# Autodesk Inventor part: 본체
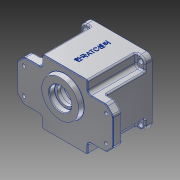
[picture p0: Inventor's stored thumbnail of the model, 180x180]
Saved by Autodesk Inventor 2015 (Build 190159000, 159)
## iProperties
Created: 2016-02
Part Number: 본체
Material: 알루미늄 6061
Document SubType Name: Modeling
Designer: Administrator
Density: 2.7 g/cm^3
Appearance: 알루미늄 - 평지
Mass: 873.852 g
Surface Area: 761.587 cm^2
Volume: 323.649 cm^3
Author: Administrator
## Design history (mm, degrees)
sketch "스케치1"
  geometry: L1 (47, -47)-(-47, -47); L2 (-47, -47)-(-47, 47); L3 (-47, 47)-(47, 47); L4 (47, 47)-(47, -47); L5 (47, -47)-(-47, 47); L6 (-47, -47)-(47, 47); 1 further point
  constraints: 12 end point, 2 midpoint, 2 parallel, 1 horizontal, 1 perpendicular
  dimensions: "d0" = 94 distance of L2.end L3.end; "d1" = 94 distance of L1.end L2.end
extrude "돌출1" new body sketch "스케치1" distance "d2" = 80; taper "d3" = 0 deg
sketch "스케치2"
  geometry: L1 (47, 47)-(-47, 47) reference; L2 (-47, 47)-(-47, -47) reference; L3 (-47, -47)-(47, -47) reference; L4 (47, -47)-(47, 47) reference; L5 (-47, 47)-(-33, 47); L6 (-33, 47)-(-33, 30); L7 (-33, 30)-(-47, 30); L8 (-47, 30)-(-47, 47); L9 (47, 47)-(33, 47); L10 (33, 47)-(33, 30); L11 (33, 30)-(47, 30); L12 (47, 30)-(47, 47); L13 (47, -47)-(33, -47); L14 (33, -47)-(33, -30); L15 (33, -30)-(47, -30); L16 (47, -30)-(47, -47); L17 (-47, -47)-(-33, -47); L18 (-33, -47)-(-33, -30); L19 (-33, -30)-(-47, -30); L20 (-47, -30)-(-47, -47); 1 further point
  constraints: 32 end point, 8 parallel, 4 horizontal, 4 perpendicular, 4 point on line
  dimensions: "d4" = 60 distance between parallel lines of L19 L7; "d5" = 30 distance from line of L7 point (0, 0) (= 0.5 x d4); "d6" = 66 distance between parallel lines of L10 L6; "d7" = 33 distance from line of point (0, 0) L10 (= 0.5 x d6)
extrude "돌출2" cut sketch "스케치2" distance "d8" = 70; taper "d9" = 0 deg
fillet "모깎기1" dims "d10" = 8
sketch "스케치3"
  geometry: C1 r 3.5 at (-40, 40); C2 r 3.5 at (40, 40); C3 r 3.5 at (40, -40); C4 r 3.5 at (-40, -40); A1 r 8 centre (-39, 39) between (-39, 47) and (-47, 39) reference; A2 r 8 centre (39, 39) between (47, 39) and (39, 47) reference; A3 r 8 centre (39, -39) between (39, -47) and (47, -39) reference; A4 r 8 centre (-39, -39) between (-47, -39) and (-39, -47) reference; 1 further point
  constraints: 4 centre point
  dimensions: "d11" = 78 distance of A2.centre A1.centre (derived); "d12" = 78 distance of A3.centre A2.centre (derived); "d13" = 7 diameter of C1; "d14" = 7 diameter of C2; "d15" = 7 diameter of C3; "d16" = 7 diameter of C4; "d17" = 80 distance of C2.centre C1.centre; "d18" = 80 distance of C3.centre C2.centre; "d19" = 40 horizontal distance of point (0, 0) C2.centre (= 0.5 x d17); "d20" = 40 horizontal distance of C2.centre point (0, 0) (= 0.5 x d18); "d21" = 40 horizontal distance of C3.centre point (0, 0) (= d19); "d22" = 40 horizontal distance of point (0, 0) C1.centre; "d23" = 40 horizontal distance of C4.centre point (0, 0) (= d22); "d24" = 40 horizontal distance of point (0, 0) C4.centre (= d21)
extrude "돌출3" cut sketch "스케치3" stored distance "d25" = 67; taper "d26" = 0 deg
sketch "스케치4"
  geometry: L1 (33, -47)-(33, -30) reference; L2 (33, -30)-(47, -30) reference; L3 (47, -30)-(47, 30) reference; L4 (47, 30)-(33, 30) reference; L5 (33, 30)-(33, 47) reference; L6 (33, 47)-(-33, 47) reference; L7 (-33, 47)-(-33, 30) reference; L8 (-33, 30)-(-47, 30) reference; L9 (-47, 30)-(-47, -30) reference; L10 (-47, -30)-(-33, -30) reference; L11 (-33, -30)-(-33, -47) reference; L12 (-33, -47)-(33, -47) reference; L13 (-47, 30)-(-70, 30); L14 (-70, 30)-(-70, -30); L15 (-70, -30)-(-47, -30); L16 (-47, -30)-(-47, 30); L17 (47, 30)-(70, 30); L18 (70, 30)-(70, -30); L19 (70, -30)-(47, -30); L20 (47, -30)-(47, 30); 1 further point
  constraints: 16 end point, 4 parallel, 2 horizontal, 2 perpendicular
  dimensions: "d27" = 140 distance between parallel lines of L18 L14; "d28" = 94 distance between parallel lines of L3 L9 (derived); "d29" = 23 distance between parallel lines of L9 L14 (= -0.5 x d28 + 0.5 x d27)
extrude "돌출4" join sketch "스케치4" distance "d30" = 13; taper "d31" = 0 deg
sketch "스케치6"
  geometry: L1 (60, -19)-(-60, -19); L2 (-60, -19)-(-60, 19); L3 (-60, 19)-(60, 19); L4 (60, 19)-(60, -19); L5 (60, -19)-(-60, 19); L6 (-60, -19)-(60, 19); 5 further points
  constraints: 12 end point, 4 coincident, 2 midpoint, 2 parallel, 1 horizontal, 1 perpendicular
  dimensions: "d34" = 38 distance between parallel lines of L3 L1; "d35" = 120 distance between parallel lines of L4 L2
hole "구멍1" sketch "스케치6" at (-60, -19), (-60, 19), (60, 19), (60, -19) diameter "d36" = 5; stored, may be unused: countersink angle "d40" = 90 deg, drill point angle "d42" = 0 deg; dims "d37" = 6, "d38" = 9, "d39" = 4, "d41" = 13
chamfer "모따기1" distance "d43" = 10; stored, may be unused: second distance "d44" = 2, angle "d45" = 45 deg
sketch "스케치7"
  geometry: C1 r 28 at (0, 11); 1 further point
  constraints: 1 centre point, 1 vertical alignment
  dimensions: "d46" = 56 diameter of C1; "d47" = 11 distance of point (0, 0) C1.centre
extrude "돌출5" join sketch "스케치7" distance "d48" = 7; taper "d49" = -10 deg
fillet "모깎기2" dims "d50" = 5
sketch "스케치8"
  geometry: C1 r 43 at (0, 0); 1 further point
  constraints: 1 centre point, 1 coincident
  dimensions: "d51" = 86 diameter of C1
extrude "돌출6" cut sketch "스케치8" distance "d52" = 9; taper "d53" = 0 deg
sketch "스케치9"
  geometry: A1 r 40 centre (0, 0) between (-39.148, -8.214) and (39.148, -8.214); A2 r 36 centre (0, 0) between (36, 0) and (-36, 0); A3 r 4 centre (36, 0) between (35.852, 3.997) and (35.852, -3.997); A4 r 4 centre (-36, 0) between (-35.852, -3.997) and (-35.852, 3.997); A5 r 3.5 centre (35.722, -7.495) between (39.148, -8.214) and (35.778, -3.995); A6 r 3.5 centre (35.722, 7.495) between (35.852, 3.997) and (39.148, 8.214); A7 r 3.5 centre (-35.722, -7.495) between (-35.852, -3.997) and (-39.148, -8.214); A8 r 3.5 centre (-35.722, 7.495) between (-39.148, 8.214) and (-35.852, 3.997); A9 r 40 centre (0, 0) between (-40, 0) and (-39.148, -8.214); A10 r 40 centre (0, 0) between (-39.148, 8.214) and (-40, 0); A11 r 4 centre (-36, 0) between (-40, 0) and (-35.852, -3.997); A12 r 4 centre (-36, 0) between (-35.852, 3.997) and (-40, 0); A13 r 40 centre (0, 0) between (39.148, -8.214) and (39.148, 8.214); A14 r 40 centre (0, 0) between (39.148, 8.214) and (-39.148, 8.214); A15 r 4 centre (36, 0) between (40, 0) and (35.852, 3.997); A16 r 4 centre (36, 0) between (35.852, -3.997) and (40, 0); 1 further point
  constraints: 38 point on circle, 16 centre point, 8 tangent, 2 coincident, 2 horizontal alignment
  dimensions: "d54" = 80 diameter of A1; "d55" = 36 radius of A2; "d56" = 4 radius of A3; "d57" = 4 radius of A4; "d58" = 3.5 radius of A5; "d59" = 3.5 radius of A6; "d60" = 3.5 radius of A8; "d61" = 3.5 radius of A7
extrude "돌출7" cut sketch "스케치9" distance "d62" = 62; taper "d63" = 0 deg
fillet "모깎기3" dims "d67" = 2
sketch "스케치11"
  geometry: L1 (-33, 45)-(-33, 35) reference; L2 (-38, 30)-(-57.929, 30) reference; L3 (-68.536, 21.464)-(-61.464, 28.536) reference; L4 (-70, 17.929)-(-70, -17.929) reference; L5 (-61.464, -28.536)-(-68.536, -21.464) reference; L6 (-57.929, -30)-(-38, -30) reference; L7 (-33, -35)-(-33, -45) reference; L8 (-31, -47)-(31, -47) reference; L9 (33, -45)-(33, -35) reference; L10 (38, -30)-(57.929, -30) reference; L11 (68.536, -21.464)-(61.464, -28.536) reference; L12 (70, -17.929)-(70, 17.929) reference; L13 (61.464, 28.536)-(68.536, 21.464) reference; L14 (57.929, 30)-(38, 30) reference; L15 (33, 35)-(33, 45) reference; L16 (31, 47)-(-31, 47) reference; L17 (31, -46)-(-31, -46); L18 (-32, -45)-(-32, -35); L19 (-38, -29)-(-57.929, -29); L20 (-60.757, -27.828)-(-67.828, -20.757); L21 (-69, -17.929)-(-69, 17.929); L22 (-67.828, 20.757)-(-60.757, 27.828); L23 (-57.929, 29)-(-38, 29); L24 (-32, 35)-(-32, 45); L25 (-31, 46)-(31, 46); L26 (32, 45)-(32, 35); L27 (38, 29)-(57.929, 29); L28 (60.757, 27.828)-(67.828, 20.757); L29 (69, 17.929)-(69, -17.929); L30 (67.828, -20.757)-(60.757, -27.828); L31 (57.929, -29)-(38, -29); L32 (32, -35)-(32, -45); C1 r 28 at (0, 11) reference; C2 r 2.5 at (60, -19) reference; C3 r 2.5 at (-60, 19) reference; C4 r 2.5 at (-60, -19) reference; C5 r 2.5 at (60, 19) reference; A1 r 2 centre (-31, 45) between (-31, 47) and (-33, 45) reference; A2 r 5 centre (-38, 35) between (-38, 30) and (-33, 35) reference; A3 r 5 centre (-57.929, 25) between (-57.929, 30) and (-61.464, 28.536) reference; A4 r 5 centre (-65, 17.929) between (-68.536, 21.464) and (-70, 17.929) reference; A5 r 5 centre (-65, -17.929) between (-70, -17.929) and (-68.536, -21.464) reference; A6 r 5 centre (-57.929, -25) between (-61.464, -28.536) and (-57.929, -30) reference; A7 r 5 centre (-38, -35) between (-33, -35) and (-38, -30) reference; A8 r 2 centre (-31, -45) between (-33, -45) and (-31, -47) reference; A9 r 2 centre (31, -45) between (31, -47) and (33, -45) reference; A10 r 5 centre (38, -35) between (38, -30) and (33, -35) reference; A11 r 5 centre (57.929, -25) between (57.929, -30) and (61.464, -28.536) reference; A12 r 5 centre (65, -17.929) between (68.536, -21.464) and (70, -17.929) reference; A13 r 5 centre (65, 17.929) between (70, 17.929) and (68.536, 21.464) reference; A14 r 5 centre (57.929, 25) between (61.464, 28.536) and (57.929, 30) reference; A15 r 5 centre (38, 35) between (33, 35) and (38, 30) reference; A16 r 2 centre (31, 45) between (33, 45) and (31, 47) reference; A17 r 1 centre (-31, -45) between (-32, -45) and (-31, -46); A18 r 6 centre (-38, -35) between (-32, -35) and (-38, -29); A19 r 4 centre (-57.929, -25) between (-60.757, -27.828) and (-57.929, -29); A20 r 4 centre (-65, -17.929) between (-69, -17.929) and (-67.828, -20.757); A21 r 4 centre (-65, 17.929) between (-67.828, 20.757) and (-69, 17.929); A22 r 4 centre (-57.929, 25) between (-57.929, 29) and (-60.757, 27.828); A23 r 6 centre (-38, 35) between (-38, 29) and (-32, 35); A24 r 1 centre (-31, 45) between (-31, 46) and (-32, 45); A25 r 1 centre (31, 45) between (32, 45) and (31, 46); A26 r 6 centre (38, 35) between (32, 35) and (38, 29); A27 r 4 centre (57.929, 25) between (60.757, 27.828) and (57.929, 29); A28 r 4 centre (65, 17.929) between (69, 17.929) and (67.828, 20.757); A29 r 4 centre (65, -17.929) between (67.828, -20.757) and (69, -17.929); A30 r 4 centre (57.929, -25) between (57.929, -29) and (60.757, -27.828); A31 r 6 centre (38, -35) between (38, -29) and (32, -35); A32 r 1 centre (31, -45) between (31, -46) and (32, -45); 1 further point
  constraints: 32 end point, 32 point on circle, 16 centre point, 31 other
  dimensions: "d68" = 1 distance between parallel lines of L16 L25
extrude "돌출9" cut sketch "스케치11" distance "d69" = 1; taper "d70" = 0 deg
sketch "스케치12"
  geometry: A1 r 21 centre (0, -11) between (-12.163, 6.119) and (12.163, 6.119); A2 r 15 centre (0, 20) between (11.584, 10.47) and (-11.584, 10.47); A3 r 3 centre (13.901, 8.565) between (11.584, 10.47) and (12.163, 6.119); A4 r 3 centre (-13.901, 8.565) between (-12.163, 6.119) and (-11.584, 10.47); 1 further point
  constraints: 8 point on circle, 4 centre point, 4 tangent, 2 vertical alignment, 1 equal radius
  dimensions: "d71" = 21 radius of A1; "d72" = 11 distance of point (0, 0) A1.centre; "d73" = 15 radius of A2; "d74" = 20 distance of A2.centre point (0, 0); "d75" = 3 radius of A3
extrude "돌출10" join sketch "스케치12" distance "d76" = 7; taper "d77" = 0 deg
hole "구멍3" diameter "d91" = 25; stored, may be unused: countersink angle "d95" = 90 deg, drill point angle "d97" = 0 deg; dims "d89" = 10, "d90" = 10, "d92" = 6, "d93" = 35, "d94" = 10, "d96" = 8
sketch "스케치13"
  geometry: C1 r 12.5 at (0, 0) reference; C2 r 16 at (0, 0); 1 further point
  constraints: 1 centre point, 1 coincident
  dimensions: "d98" = 16 radius of C2
extrude "돌출11" cut sketch "스케치13" distance "d99" = 8; taper "d100" = 0 deg
fillet "모깎기6" dims "d101" = 0.3
chamfer "모따기2" distance "d102" = 1; stored, may be unused: second distance "d103" = 2, angle "d104" = 45 deg
sketch "스케치14"
  geometry: A1 r 4 centre (36, 0) between (35.852, 3.997) and (35.852, -3.997) reference; A2 r 4 centre (-36, 0) between (-35.852, -3.997) and (-35.852, 3.997) reference; 3 further points
  constraints: 2 coincident
hole "구멍4" sketch "스케치14" at (36, 0), (-36, 0) diameter "d105" = 3.242; stored, may be unused: countersink angle "d109" = 90 deg, drill point angle "d111" = 118 deg; dims "d106" = 7, "d107" = 35, "d108" = 10, "d110" = 9
fillet "모깎기7" dims "d112" = 2
sketch "스케치15" dims "d0" = 94, "d1" = 94
  geometry: L1 (78, 0)-(0, 0) reference; 3 further points
  constraints: 1 midpoint, 1 vertical alignment, 1 other
  dimensions: "d113" = 40 distance of point (39, 0) point (39, -40)
feature "엠보싱1" sketch "스케치15" dims "d0" = 94, "d1" = 94, "d4" = 60, "d5" = 30 (= 0.5 x d4), "d6" = 66, "d7" = 33 (= 0.5 x d6), "d114" = 0.5, "d115" = 0
fillet "모깎기8" dims "d116" = 0.3
sketch "Sketch18"
  geometry: C1 r 18.5 at (0, -11) reference; C2 r 11 at (0, 20); A1 r 3 centre (13.901, 8.565) between (11.584, 10.47) and (12.163, 6.119) reference; A2 r 15 centre (0, 20) between (11.584, 10.47) and (-11.584, 10.47) reference; A3 r 3 centre (-13.901, 8.565) between (-12.163, 6.119) and (-11.584, 10.47) reference; A4 r 21 centre (0, -11) between (-12.163, 6.119) and (12.163, 6.119) reference; 1 further point
  constraints: 1 centre point, 1 coincident
  dimensions: "d121" = 22 diameter of C2
extrude "Extrusion13" cut sketch "Sketch18" distance "d122" = 7; taper "d123" = 0 deg
sketch "Sketch19"
  geometry: C1 r 11 at (0, 0) reference; C2 r 9.5 at (0, 0); 1 further point
  constraints: 1 centre point, 1 coincident
  dimensions: "d124" = 19 diameter of C2
extrude "Extrusion14" cut sketch "Sketch19" distance "d125" = 1; taper "d126" = 0 deg
fillet "Fillet9" dims "d127" = 2
fillet "Fillet10" dims "d128" = 0.3
node "솔리드1"
node "투영된 루프1"
node "투영된 루프3"
node "Projected Loop6"
node "Projected Loop7"
